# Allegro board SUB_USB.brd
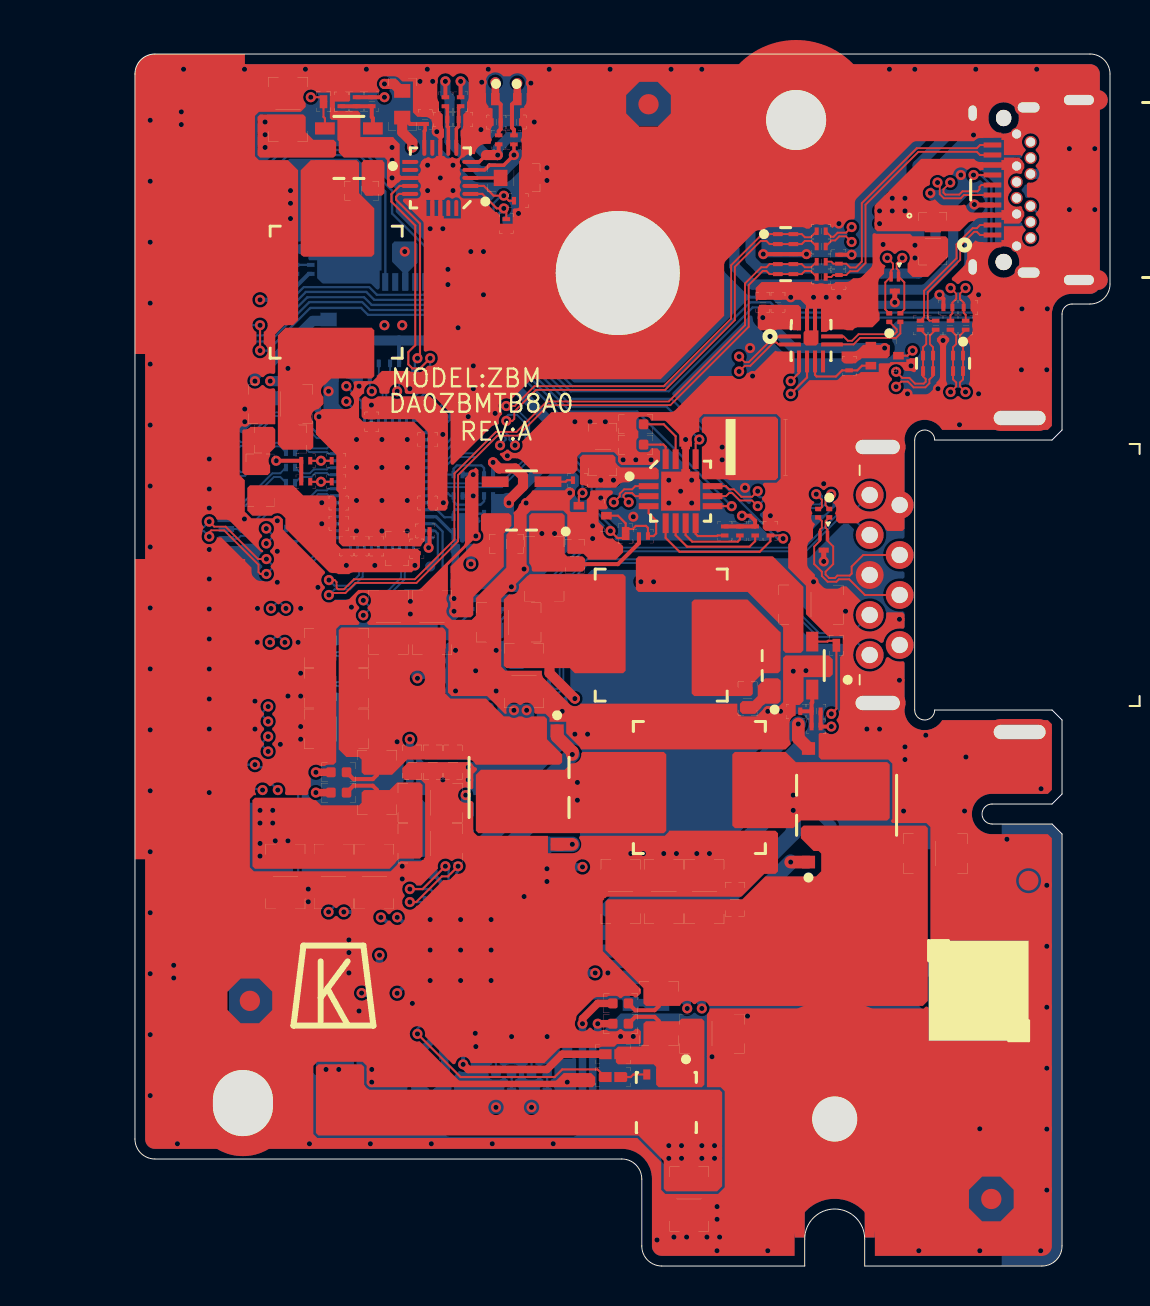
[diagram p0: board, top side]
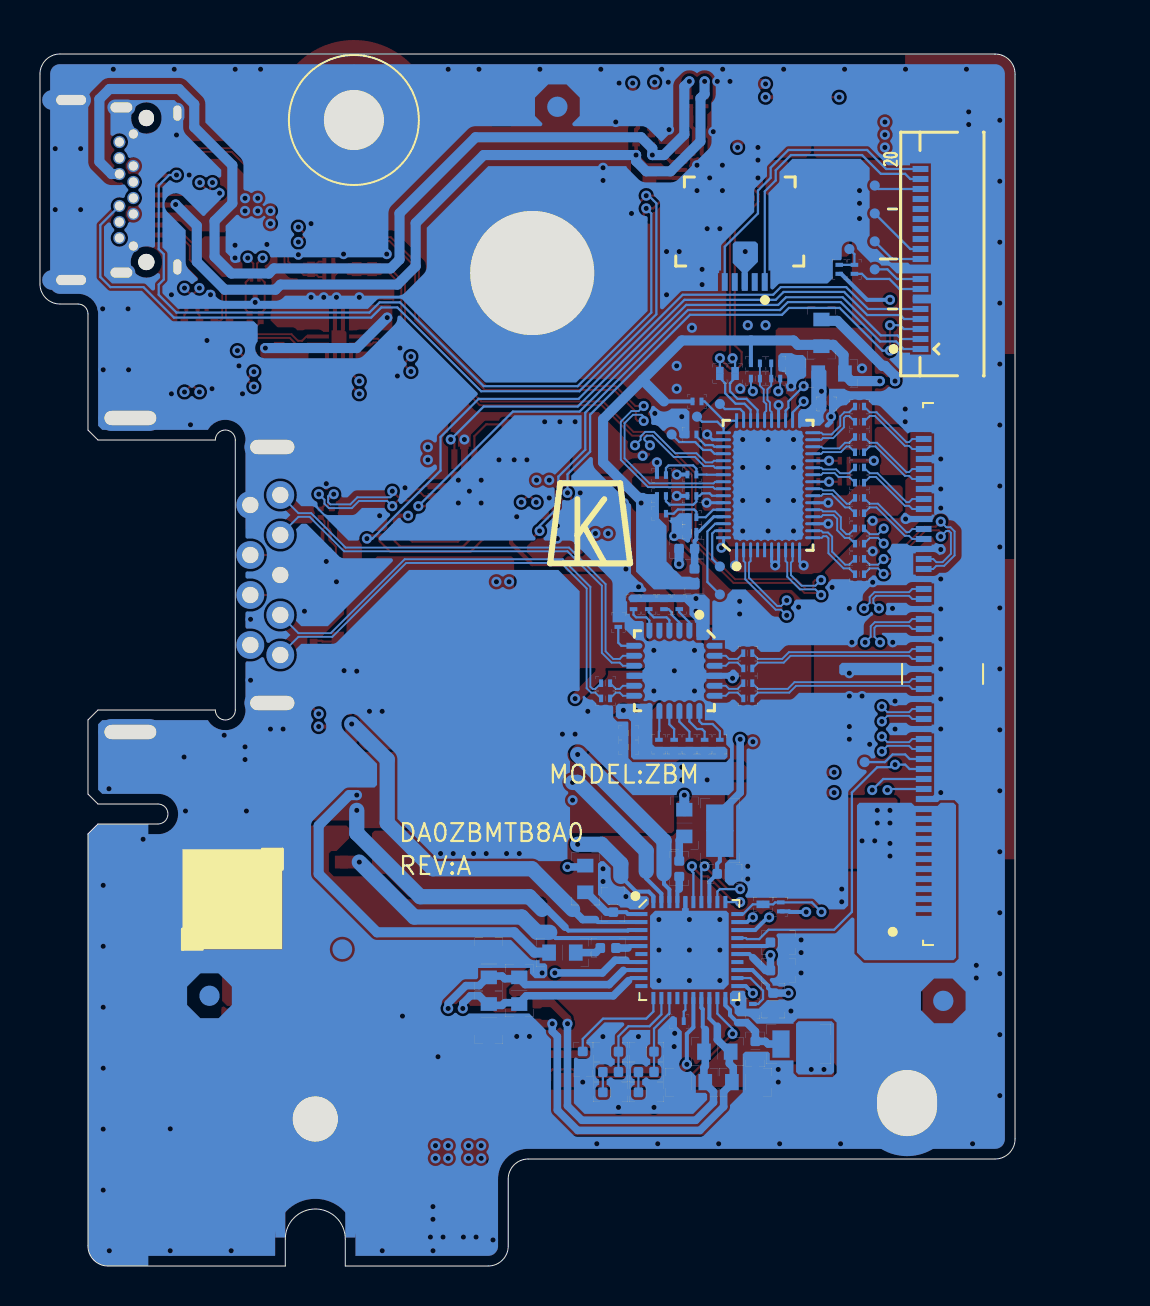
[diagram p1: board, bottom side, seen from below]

Outline 48.77 x 60.6 mm; copper layers: TOP, SGND, IN1, IN2, IN3, IN4, IN5, BOTTOM. Coordinates in mm from the lower left corner of the outline.
Outline path: 0,59.6 arc(0.29,60.31) 1,60.6 47.77,60.6 arc(48.48,60.31) 48.77,59.6 48.77,49.1 arc(48.48,48.39) 47.77,48.1 46.87,48.1 arc(46.52,47.95) 46.37,47.6 46.37,41.8 45.87,41.3 40,41.3 arc(39.5,41.8) 39,41.3 39,27.8 arc(39.5,27.3) 40,27.8 45.87,27.8 46.37,27.3 46.37,23.6 45.87,23.1 42.87,23.1 arc(42.37,22.6) 42.87,22.1 45.87,22.1 46.37,21.6 46.37,1 arc(46.08,0.29) 45.37,0 36.5,0 36.5,1.35 arc(35,2.85) 33.5,1.35 33.5,0 26.35,0 arc(25.64,0.29) 25.35,1 25.35,4.35 arc(25.06,5.06) 24.35,5.35 1,5.35 arc(0.29,5.64) 0,6.35 0,59.6

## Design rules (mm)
constraint set DEFAULT: min track width 0.109
net group W20-T1234B: nets PP3300_USB_C1_G PP3300_USB_C1_U
net group DFP-S3.5(4.2: nets USB_A1_SSRX_C_N USB_A1_SSRX_C_P USB_A1_SSRX_N USB_A1_SSRX_P USB_A1_SSRX_U_N USB_A1_SSRX_U_P USB_A1_SSTX_C_N USB_A1_SSTX_C_P USB_A1_SSTX_N USB_A1_SSTX_P USB_A1_SSTX_U_N USB_A1_SSTX_U_P USB_C1_AUX_DC_N USB_C1_AUX_DC_P USB_C1_ML0_C_N USB_C1_ML0_C_P USB_C1_ML0_N USB_C1_ML0_P USB_C1_ML1_C_N USB_C1_ML1_C_P USB_C1_ML1_N USB_C1_ML1_P USB_C1_ML2_C_N USB_C1_ML2_C_P USB_C1_ML2_N USB_C1_ML2_P USB_C1_ML3_C_N USB_C1_ML3_C_P USB_C1_ML3_N USB_C1_ML3_P USB_C1_RX2_CON_N USB_C1_RX2_CON_P USB_C1_SSRX_C_N USB_C1_SSRX_C_P USB_C1_SSTX_C_N USB_C1_SSTX_C_P USB_C1_TX2_CON_N USB_C1_TX2_CON_P USB_C1_USB2_U_N USB_C1_USB2_U_P
net group W20-T124B: nets USB_C1_CC1 USB_C1_CC1_C USB_C1_CC2 USB_C1_CC2_C

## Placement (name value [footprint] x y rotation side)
C1  0.22u/6.3V_2  [C0201]  13.37 29.14 0 bottom
C2  0.22u/6.3V_2  [C0201]  13.37 28.38 0 bottom
C3  0.1u/6.3V_2  [C0201]  19.34 26.67 0 bottom
C4  0.1u/6.3V_2  [C0201]  19.34 25.93 0 bottom
C5  0.22u/6.3V_2  [C0201]  20.48 28.38 0 bottom
C6  0.22u/6.3V_2  [C0201]  20.48 29.14 0 bottom
C7  1u/6.3V_2  [C0201]  14.51 36.75 180 top
C8  0.1u/6.3V_2  [C0201]  9.43 43.1 180 bottom
C22  22p/50V_2  [C0201]  11.84 58.22 270 top
C23  *220p/25V_2  [C0201]  19.08 57.2 0 top
C24  *220p/25V_2  [C0201]  18.07 57.2 180 top
C25  22u/10V_8  [C0805]  18.7 32.18 0 top
C98  22u/6.3V_6  [C0603]  23.4 40.82 270 top
C146  0.22u/10V_2  [C0201]  7.78 37.64 0 bottom
C156  0.22u/6.3V_2  [C0201]  13.37 29.88 0 bottom
C157  0.22u/6.3V_2  [C0201]  13.37 30.64 0 bottom
C160  150u/6.3V_3528H1.9  [C3528]  32.54 40.94 180 top
C161  0.1u/25V_2  [C0201]  11.97 44.37 0 bottom
C162  0.1u/25V_2  [C0201]  12.99 44.37 180 bottom
C165  0.1u/6.3V_2  [C0201]  31.4 48.18 90 top
C166  1u/6.3V_2  [C0201]  32.16 48.18 90 top
C167  1u/6.3V_2  [C0201]  14.51 57.33 90 top
C168  0.33u/25V_2  [C0201]  40.79 47.04 90 top
C169  0.33u/25V_2  [C0201]  41.55 47.04 90 top
C170  0.22u/10V_2  [C0201]  39.29 47.04 90 top
C171  0.22u/10V_2  [C0201]  40.05 47.04 90 top
C172  0.33u/25V_2  [C0201]  34.32 49.45 0 top
C173  0.33u/25V_2  [C0201]  34.32 50.21 0 top
C175  0.22u/10V_2  [C0201]  34.32 50.98 0 top
C176  0.22u/10V_2  [C0201]  34.32 51.74 0 top
C177  0.1u/50V_6  [C0603]  18.96 54.41 180 top
C181  0.1u/50V_6  [C0603]  39.91 51.36 90 top
C182  10u/35V_8  [C0805]  27.72 3.35 90 top
C183  22u/25V_8  [C0805]  40.04 20.62 180 top
C187  4.7u/6.3V_4  [C0402_2]  11.84 14.78 0 bottom
C188  22u/25V_8  [C0805]  24.29 18.72 270 top
C189  4.7u/25V_6  [C0603]  14.89 10.72 180 bottom
C192  22u/25V_8  [C0805]  28.48 18.72 270 top
C193  22u/25V_8  [C0805]  26.45 18.72 270 top
C194  0.1u/25V_4  [C0402]  30 18.34 270 top
C197  0.47u/50V_6  [C0603]  22.64 15.67 0 bottom
C198  0.47u/50V_6  [C0603]  16.54 22.15 90 bottom
C199  0.1u/25V_4  [C0402]  13.88 25.2 90 top
C200  4.7u/10V_4  [C0402_2]  12.1 13.26 90 bottom
C201  22u/25V_8  [C0805]  12.68 32.18 270 top
C202  4.7u/10V_4  [C0402_2]  20.1 18.08 270 bottom
C203  22u/25V_8  [C0805]  14.87 32.18 270 top
C204  22u/25V_8  [C0805]  10.07 30.91 0 top
C213  22u/25V_8  [C0805]  10.07 26.85 0 top
C214  22u/25V_8  [C0805]  10.07 28.88 0 top
C215  22u/25V_8  [C0805]  11.97 19.48 90 top
C216  22u/25V_8  [C0805]  14.76 21.13 180 top
C217  22u/25V_8  [C0805]  14.76 23.16 180 top
C218  22u/25V_8  [C0805]  9.94 19.48 90 top
C219  22u/25V_8  [C0805]  7.53 19.48 90 top
C249  22u/25V_8  [C0805]  7.65 57.83 270 top
C250  22u/25V_8  [C0805]  33.81 33.07 180 top
C254  0.1u/50V_4  [C0402]  30.64 28.37 270 top
C255  0.1u/50V_4  [C0402]  11.34 53.77 0 top
C258  100p/25V_2  [C0201]  34.07 27.74 180 top
C259  22u/10V_8  [C0805]  7.27 43.1 0 top
C260  22u/10V_8  [C0805]  19.46 29.51 90 top
C748  0.01u/10V_2  [C0201]  11.84 42.21 270 top
C1006  0.068u/50V_6  [C0603]  13.49 9.19 0 bottom
C1007  4700p/50V_4  [C0402]  20.23 8.69 0 bottom
C1008  *0.1u/25V_4  [C0402]  20.23 10.72 180 bottom
C1009  4700p/50V_4  [C0402]  18.45 8.69 0 bottom
C1010  *0.1u/25V_4  [C0402]  18.45 10.72 180 bottom
C1011  4.7u/6.3V_4  [C0402_2]  11.84 16.18 0 bottom
C1012  2.2u/10V_4  [C0402]  14.51 19.61 0 bottom
C1013  *0.068u/50V_6  [C0603]  16.16 9.19 180 bottom
C1014  1u/25V_4  [C0402]  14.89 25.2 90 top
C1015  1u/25V_4  [C0402]  15.91 25.2 90 top
C1016  *0.068u/50V_6  [C0603]  26.32 12.43 90 bottom
C1017  4.7u/25V_6  [C0603]  24.8 13.77 270 bottom
C1018  0.068u/50V_6  [C0603]  26.32 15.1 270 bottom
C1019  1u/10V_4  [C0402]  22 35.48 270 top
C1020  1u/10V_4  [C0402]  18.57 36.12 180 top
C1021  1u/6.3V_2  [C0201]  16.16 39.57 180 bottom
C1022  4.7u/6.3V_4  [C0402_2]  13.11 35.86 270 top
C1023  0.01u/10V_2  [C0201]  14.64 41.32 180 top
C1024  *0.1u/25V_4  [C0402]  12.99 10.84 90 bottom
C1025  0.01u/10V_2  [C0201]  14.64 38.15 180 top
C1026  0.1u/6.3V_2  [C0201]  10.19 38.15 0 top
C1027  0.1u/6.3V_2  [C0201]  10.19 37.13 0 top
C1028  0.1u/6.3V_2  [C0201]  14.1 35.86 90 top
C1029  0.1u/6.3V_2  [C0201]  11.34 35.99 90 top
C1030  0.1u/6.3V_2  [C0201]  10.57 35.99 90 top
C1031  1u/6.3V_2  [C0201]  16.16 36.71 180 bottom
C1032  0.22u/10V_2  [C0201]  7.78 38.4 0 bottom
C1033  0.22u/10V_2  [C0201]  7.78 39.17 0 bottom
C1034  0.22u/10V_2  [C0201]  7.78 39.93 0 bottom
C1035  0.22u/10V_2  [C0201]  7.78 40.69 0 bottom
C1036  0.22u/10V_2  [C0201]  7.78 41.45 0 bottom
C1037  0.22u/10V_2  [C0201]  7.78 42.21 0 bottom
C1038  0.22u/10V_2  [C0201]  7.78 42.98 0 bottom
C1039  0.22u/10V_2  [C0201]  7.78 35.36 0 bottom
C1040  0.22u/10V_2  [C0201]  7.78 34.59 0 bottom
C1041  0.22u/10V_2  [C0201]  7.78 36.88 0 bottom
C1042  0.22u/10V_2  [C0201]  7.78 36.12 0 bottom
C1046  0.01u/10V_2  [C0201]  12.1 35.99 90 top
C1047  22u/25V_8  [C0805]  28.86 11.61 180 top
CN1  50506-00601-V01  [FPC-50506-00601-V01-6P-L]  13.77 52.25 0 bottom
D1  PE3620M1Q  [D-1X0_6-D24V0L1B2LPS]  38.26 51.74 270 top
D7  PUSB3FR4  [ESD10-2_5X1-5-0_5H]  40.42 45.13 180 top
D8  PUSB3FR4  [ESD10-2_5X1-5-0_5H]  32.54 50.6 270 top
D2741  PESD5V0X2UM  [D3-1X0_6-3P]  38.01 49.07 90 top
D2744  PESD5V0X2UM  [D3-1X0_6-3P]  34.45 36.12 90 top
D2745  PJE24VM5FN2  [D-1X0_6-2P-PJE24VM5FN2]  17.69 58.34 180 top
D2746  PJE24VM5FN2  [D-1X0_6-2P-PJE24VM5FN2]  19.46 58.34 0 top
HOLE18  *2D-BARCODE-5X5-S  [2D-BARCODE-5X5-S]  39.15 18.34 180 bottom
HOLE19  *2D-BARCODE-5X5-S  [2D-BARCODE-5X5-S]  42.2 13.77 90 top
HOLE20  *H-TC315IBC217D118P2  [H-TC315IBC217D118P2]  33.07 57.3 0 top
HOLE21  *H-C354D244P2  [H-C354D244P2]  24.15 49.65 0 top
HOLE22  *H-O197X209D118X130P2  [H-O197X209D118X130P2]  5.4 8.15 0 top
HOLE23  *H-TS3BS3D146P2  [H-TS3BS3D146P2]  35 7.35 0 top
HOLE24  *SPAD-ZBM-USB_B-1NP  [SPAD-ZBM-USB_B-1NP]  2.75 53.1 0 top
HOLE25  *SPAD-RE217X591NP  [SPAD-RE217X591NP]  2.76 27.84 0 top
HOLE26  *SPAD-C354NP  [SPAD-C354NP]  18 14.85 0 top
HOLE27  *SPAD-ZBM-USB_B-3NP  [SPAD-ZBM-USB_B-3NP]  44.86 11.05 0 bottom
J10  30154-00902-V01  [UB3-30154-00902-V01-9P]  44.25 34.55 90 top
J11  UT11113-1220Q-7H  [UB31-UT11113-1220Q-7H-24P]  43.45 53.8 90 top
J12  50696-0200M-V02  [50696-0200M-V02-20P-L]  2.23 50.6 90 bottom
J13  196650-50041-3  [FPC-196650-50041-3-50P-L]  1.97 29.6 90 bottom
L5  NFP0QHB542HS2D  [FILTER-NFP0QHB542HS2D-4P-SMT]  38.01 47.42 0 top
L6  NFP0QHB542HS2D  [FILTER-NFP0QHB542HS2D-4P-SMT]  34.45 37.64 180 top
L9  2.2uH_7.3x6.8x2.0  [L6_6X6_6-1_8H]  28.23 23.93 180 top
L15  6.8uH_6.6x7.4x1.8  [L6_6X6_6-1_6H]  10.07 48.69 270 top
L16  6.8uH_6.6x7.4x1.8  [L6_6X6_6-1_6H]  26.32 31.55 180 top
NOREF  -  [unnamed]  5.75 13.26 0 top
NOREF#2  -  [#2]  9.94 14.02 0 top
NOREF#3  -  [#2]  111.41 -8.21 0 top
NOREF#4  -  [#2]  60.61 -48.85 0 top
NOREF#5  -  [unnamed]  42.83 3.35 0 top
NOREF#6  -  [unnamed]  25.69 58.09 0 top
NOREF#7  -  [#2]  21.24 37.13 180 bottom
NOREF#8  -  [unnamed]  22.89 57.96 180 bottom
NOREF#9  -  [unnamed]  40.29 13.51 180 bottom
NOREF#10  -  [unnamed]  3.59 13.26 180 bottom
Q1  DMG1012T-7  [SOT23-1_38-5-3P]  37.5 45.52 180 top
Q38  PJE138K  [SOT23-1_38-5-3P]  22.89 37.51 180 top
Q1000  AONR32314  [DFN-8L-3X3-65-5P-0_9H]  26.58 8.18 90 top
Q1001  AON6998  [POWER-5X6-1_27-7P-0_8H]  35.59 23.04 0 top
Q1008  AON6998  [POWER-5X6-1_27-7P-0_8H]  19.21 23.93 180 top
R4  *0_5%_2  [R0201]  15.53 26.08 90 bottom
R5  *0_5%_2  [R0201]  17.05 26.08 90 bottom
R6  *0_5%_2  [R0201]  14.76 26.08 90 bottom
R7  *0_5%_2  [R0201]  16.29 26.08 90 bottom
R8  *4.99K_1%_2  [R0201]  19.84 32.18 90 bottom
R9  *0_5%_2  [R0201]  16.8 33.07 90 bottom
R10  *0_5%_2  [R0201]  18.32 33.07 90 bottom
R11  *0_5%_2  [R0201]  19.08 33.07 90 bottom
R12  *0_5%_2  [R0201]  17.56 33.07 90 bottom
R15  *Short_0201  [S0201]  14 44.63 90 bottom
R16  *Short_0201  [S0201]  14.76 44.63 90 bottom
R20  0_5%_6  [R0603]  13.37 58.09 90 top
R21  0_5%_6  [R0603]  9.68 46.66 90 bottom
R22  499K_1%_2  [R0201]  11.72 17.96 270 bottom
R23  *Short_0201  [S0201]  9.43 58.22 270 top
R24  *Short_0201  [S0201]  35.08 31.04 90 top
R25  100K_1%_2  [R0201]  35.72 45.01 270 top
R37  1K_1%_2  [R0201]  8.03 49.83 90 bottom
R84  10K_5%_2  [R0201]  17.69 39.55 180 bottom
R182  0_5%_6  [R0603]  6.26 39.29 90 top
R210  100K_5%_2  [R0201]  12.99 45.13 180 bottom
R211  100K_5%_2  [R0201]  11.97 45.13 180 bottom
R220  220K_1%_2  [R0201]  40.66 47.93 180 top
R221  220K_1%_2  [R0201]  41.68 47.93 0 top
R222  220K_1%_2  [R0201]  35.21 49.33 270 top
R223  220K_1%_2  [R0201]  35.21 50.34 90 top
R224  2_1%_4  [R0402]  24.29 12.11 0 top
R226  0_5%_4  [R0402]  24.29 13.13 180 top
R227  1.65K_1%_4  [R0402]  21.62 10.34 90 bottom
R266  0_1%_6  [R0603]  7.27 41.35 0 top
R267  0_1%_8  [R0805]  20.48 34.85 270 top
R268  100K_1%_2  [R0201]  11.08 58.22 270 top
R269  100K_1%_2  [R0201]  10.32 58.22 90 top
R270  13.7K_1%_2  [R0201]  33.05 27.74 180 top
R271  102K_1%_2  [R0201]  34.07 26.97 180 top
R375  100K_5%_2  [R0201]  31.78 36.75 90 top
R1000  *Short_0402  [S0402]  23.91 9.45 0 top
R1001  0_1%_8  [R0805]  10.83 11.1 180 bottom
R1002  *Short_0402  [S0402]  23.91 10.59 0 top
R1003  6.98K_1%_4  [R0402]  20.23 9.7 180 bottom
R1004  4.7_1%_6  [R0603]  21.5 19.35 270 bottom
R1005  3.48K_1%_4  [R0402]  18.45 9.7 180 bottom
R1006  0_5%_4  [R0402]  20.35 15.9 0 bottom
R1007  0_5%_4  [R0402]  16.8 19.86 270 bottom
R1008  *10K_1%_2  [R0201]  13.11 12.88 90 bottom
R1009  133K_1%_2  [R0201]  16.8 12.24 0 bottom
R1010  *Short_0201  [S0201]  12.61 18.08 180 bottom
R1011  *Short_0805  [S0805]  14.76 21.77 270 bottom
R1012  0_5%_4  [R0402]  10.19 24.69 180 top
R1013  2_1%_4  [R0402]  10.19 23.67 0 top
R27288  2M_5%_2  [R0201]  19.18 53.26 0 top
R27302  100K_5%_2  [R0201]  31.02 36.75 270 top
R27303  100K_5%_2  [R0201]  30.26 36.75 270 top
R27304  100K_5%_2  [R0201]  29.5 36.75 270 top
R27305  29.4K_1%_4  [R0402]  25.05 41.07 0 top
R27306  48.7K_1%_4  [R0402]  25.05 42.09 0 top
R27307  100K_5%_2  [R0201]  25.43 36.5 0 top
R27309  4.99K_1%_2  [R0201]  16.16 41.58 0 bottom
R27310  0_5%_4  [R0402]  16.03 34.47 270 bottom
R27311  *0_5%_4  [R0402]  16.42 35.86 0 bottom
R27312  0_5%_6  [R0603]  9.18 44.63 180 bottom
R27313  *4.7K_1%_2  [R0201]  8.54 39.21 0 top
R27314  *4.7K_1%_2  [R0201]  10.07 39.21 0 top
R27315  *4.7K_1%_2  [R0201]  8.54 40.26 0 top
R27316  *4.7K_1%_2  [R0201]  10.07 40.26 0 top
R27317  *4.7K_1%_2  [R0201]  17.69 37.62 180 bottom
R27318  *4.7K_1%_2  [R0201]  16.16 37.44 0 bottom
R27319  *4.7K_1%_2  [R0201]  17.69 38.5 180 bottom
R27320  *4.7K_1%_2  [R0201]  16.16 38.5 0 bottom
R27325  2M_5%_2  [R0201]  18.57 52.12 270 top
R27327  4.7K_1%_2  [R0201]  15.91 43.23 0 bottom
R27329  100K_5%_2  [R0201]  8.8 49.83 90 bottom
R27331  10K_1%_2  [R0201]  22.13 39.29 0 top
R27332  *4.7K_1%_2  [R0201]  17.81 26.08 90 bottom
R27333  *Short_0201  [S0201]  24.54 36.63 90 top
R91340  0_5%_2  [R0201]  18.96 56.31 90 top
R91341  0_5%_2  [R0201]  18.19 56.31 90 top
R91345  *0_5%_2  [R0201]  16.29 58.22 90 top
R91346  *0_5%_2  [R0201]  15.53 58.22 90 top
R91347  0_5%_2  [R0201]  15.4 57.33 0 top
R91348  0_5%_2  [R0201]  16.42 57.33 180 top
TP93  *TP  [TP2050]  14.76 43.1 180 bottom
TP95  *TP  [TP2050]  15.91 42.47 180 bottom
TP99  *TP  [TP2050]  14.76 34.97 180 bottom
TP100  *TP  [TP2050]  14.76 33.58 180 bottom
TP103  *TP  [TP2050]  17.18 41.58 180 bottom
TP105  *TP  [TP2050]  7.02 49.83 180 bottom
TP106  *TP  [TP2050]  8.29 50.85 180 bottom
TP107  *TP  [TP2050]  7.02 51.23 180 bottom
TP108  *TP  [TP2050]  7.02 52.63 180 bottom
TP109  *TP  [TP2050]  7.02 54.02 180 bottom
TP110  *TP  [TP2050]  7.53 25.2 180 bottom
U1  PS8719ETQFN24GTR2-A0  [QFN24-4X4-5-25P-9DBL02]  17.04 29.76 0 bottom
U2  PS8762QFN52GTR-A3  [QFN52-6_5X4_5-35-53P-0_8H]  12.35 39.04 180 bottom
U3  SY21041ABC  [SOT23-2_85-95-6P-1_4H]  10.7 55.93 0 top
U4  SY21113IADC  [SOT23-2_85-95-6P-1H]  32.93 30.02 270 top
U7  PI3USB9201ZTAEX  [QFN12-2X2-4]  33.81 46.28 270 top
U8  TPD6S300ARUKR  [QFN20-3X3-4-21P-TPD6S300]  15.27 54.41 90 top
U9  RAA489000ARGNP#HA0  [QFN40-5X5-4-41P-1H]  16.29 15.8 270 bottom
U18  0.01_1%_8  [R0805]  26.19 12.62 270 top
U37  SLGC55545VTR  [QFN16-3X3-5-17P-SLGC55544C]  27.29 38.74 270 top
U1000  0.01_1%_8  [R0805]  12.1 24.18 270 top
U1001  RT9078-33GJ5  [TSOT23-5-2_7955-9395-5P]  19.34 38.28 0 top

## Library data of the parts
C1-C8 C22-C25 C98 C156 C157 C161 C162 C165-C169 C172 C173 C177 C181-C183 C187-C189 C192-C194 C197-C204 C213-C219 C249 C250 C254 C255 C258-C260 C748 C1006-C1031 C1046 C1047 = CAP_NON-POL_BGM
C146 C170 C171 C175 C176 C1032-C1042 = CAP_NON-POL_V1_BGM
C160 = CAP_POL_BGM
CN1 = FFCFPC_6P_V2_BGM
D1 = TVS_DIODE_BGM
D7 D8 = PUSB3F96_10P_BGM
D2741 D2744 = PESD5V0X2UM_BGM
D2745 D2746 = TVS_DIODE_UNI_V2_BGM
HOLE18-HOLE27 = 3x2_6.1
J10 = USB3_TCR26-9V1391_13P_BGM
J11 = USB3_1_24P_8F_BGM
J12 = FFCFPC_20P_BGM
J13 = FFCFPC_50P_BGM
L5 L6 = BW_BGM
L9 L15 L16 = IND_V2_BGM
Q1 Q38 = MOS-N_3P_ESD_BGM
Q1000 = MOS-N_8P_SCH_BGM
Q1001 Q1008 = MOS-N-Dual_9P_BGM
R4-R12 R20-R22 R25 R37 R84 R182 R210 R211 R220-R224 R226 R227 R266-R271 R375 R1001 R1003-R1009 R1012 R1013 R27288 R27302-R27307 R27309-R27320 R27325 R27327 R27329 R27331 R27332 R91340 R91341 R91345-R91348 = RES_BGM
R15 R16 R23 R24 R1000 R1002 R1010 R1011 R27333 = SHORTPAD_V01_BGM
TP93 TP95 TP99 TP100 TP103 TP105-TP110 = TP_BGM
U1 = PS8719BTQFN24GTR-A0_24P_BGM
U2 = PS8802QFN52GTR-A1_52P_BGM_0
U3 = SY21041ABC_6P_V2_BGM
U4 = SY21113IADC_6P_V2_BGM
U7 = PI3USB9201ZTAEX_12P_V1_BGM
U8 = TPD6S300ARUKR_20P_BGM
U9 = ISL9237_19
U18 U1000 = R_Current_SEN_BGM
U37 = SLGC55545VTR_16P_BGM
U1001 = RT9078N-33GJ5_5P_BGM_0

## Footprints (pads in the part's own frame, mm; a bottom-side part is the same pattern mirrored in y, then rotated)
2D-BARCODE-5X5-S
  round 0.991 smd: 1(5.5,-2.5)
50696-0200M-V02-20P-L
  rect 0.305x0.787 smd: 1(-4.75,2.5) 2(-4.25,2.5) 3(-3.75,2.5) 4(-3.25,2.5) 5(-2.75,2.5) 6(-2.25,2.5) 7(-1.75,2.5) 8(-1.25,2.5) 9(-0.75,2.5) 10(-0.25,2.5) 11(0.25,2.5) 12(0.75,2.5) 13(1.25,2.5) 14(1.75,2.5) 15(2.25,2.5) 16(2.75,2.5) 17(3.25,2.5) 18(3.75,2.5) 19(4.25,2.5) 20(4.75,2.5)
  rect 0.406x0.787 smd: 21(-5.75,0) 22(5.75,0)
C0201
  rect 0.203x0.381 smd: 1(-0.225,0) 2(0.225,0)
C0402
  custom 0.12x0.12 smd: 1(0.39,0) 2(-0.39,0)
C0402_2
  custom 0.12x0.12 smd: 1(0.39,0) 2(-0.39,0)
C0603
  rect 0.686x0.813 smd: 1(0.6,0) 2(-0.6,0)
C0805
  rect 0.864x1.372 smd: 1(0.88,0) 2(-0.88,0)
C3528
  rect 1.6x2.591 smd: 1(1.5,0) 2(-1.5,0)
D3-1X0_6-3P
  rect 0.508x0.178 smd: 1(0.401,0.187) 2(0.401,-0.187)
  rect 0.254x0.508 smd: 3(-0.325,0)
D-1X0_6-2P-PJE24VM5FN2
  rect 0.432x0.61 smd: 1(-0.34,0) 2(0.34,0)
D-1X0_6-D24V0L1B2LPS
  rect 0.457x0.61 smd: 1(-0.375,0) 2(0.375,0)
DFN-8L-3X3-65-5P-0_9H
  rect 0.508x0.356 smd: 1(1.4,-0.975) 2(1.4,-0.325) 3(1.4,0.325) 4(1.4,0.975)
  custom 0.57x0.57 smd: 5(-0.51,0)
ESD10-2_5X1-5-0_5H
  rect 0.203x0.483 smd: 1(-1,-0.388) 2(-0.5,-0.388) 3(0,-0.388) 4(0.5,-0.388) 5(1,-0.388) 6(1,0.388) 7(0.5,0.388) 8(0,0.388) 9(-0.5,0.388) 10(-1,0.388)
FILTER-NFP0QHB542HS2D-4P-SMT
  rect 0.305x0.229 smd: 1(-0.278,-0.212) 2(-0.278,0.212) 3(0.278,0.212) 4(0.278,-0.212)
FPC-50506-00601-V01-6P-L
  rect 0.305x0.889 smd: 1(-1.25,3.05) 2(-0.75,3.05) 3(-0.25,3.05) 4(0.25,3.05) 5(0.75,3.05) 6(1.25,3.05)
  rect 0.991x2.007 smd: 7(-3.35,0) 8(3.35,0)
FPC-196650-50041-3-50P-L
  rect 0.305x0.787 smd: 1(-12.25,2.6) 2(-11.75,2.6) 3(-11.25,2.6) 4(-10.75,2.6) 5(-10.25,2.6) 6(-9.75,2.6) 7(-9.25,2.6) 8(-8.75,2.6) 9(-8.25,2.6) 10(-7.75,2.6) 11(-7.25,2.6) 12(-6.75,2.6) 13(-6.25,2.6) 14(-5.75,2.6) 15(-5.25,2.6) 16(-4.75,2.6) 17(-4.25,2.6) 18(-3.75,2.6) 19(-3.25,2.6) 20(-2.75,2.6) 21(-2.25,2.6) 22(-1.75,2.6) 23(-1.25,2.6) 24(-0.75,2.6) 25(-0.25,2.6) 26(0.25,2.6) 27(0.75,2.6) 28(1.25,2.6) 29(1.75,2.6) 30(2.25,2.6) 31(2.75,2.6) 32(3.25,2.6) 33(3.75,2.6) 34(4.25,2.6) 35(4.75,2.6) 36(5.25,2.6) 37(5.75,2.6) 38(6.25,2.6) 39(6.75,2.6) 40(7.25,2.6) 41(7.75,2.6) 42(8.25,2.6) 43(8.75,2.6) 44(9.25,2.6) 45(9.75,2.6) 46(10.25,2.6) 47(10.75,2.6) 48(11.25,2.6) 49(11.75,2.6) 50(12.25,2.6)
  rect 0.991x0.991 smd: 51(-13.55,0) 52(13.55,0)
H-C354D244P2
  round 9 hole 6.2: 1(0,0)
H-O197X209D118X130P2
  oval 5.004x5.309 hole 3x3.302: 1(0,0)
H-TC315IBC217D118P2
  round 8.001 hole 3: 1(0,0)
H-TS3BS3D146P2
  custom 2.25x2.25 hole 3.708: 1(0,0)
L6_6X6_6-1_6H
  rect 2.362x3.505 smd: 1(-3.025,0) 2(3.025,0)
L6_6X6_6-1_8H
  rect 2.362x3.505 smd: 1(-3.025,0) 2(3.025,0)
POWER-5X6-1_27-7P-0_8H
  rect 0.66x0.635 smd: 1(-1.905,-2.84) 5(1.905,2.84) 6(0.635,2.84) 7(-0.635,2.84) 8(-1.905,2.84)
  custom 0.488x0.488 smd: 2(0,-2.18)
  rect 3.988x2.667 smd: 9(0,0.795)
QFN12-2X2-4
  rect 0.203x1.092 smd: 1(-0.2,-1.05) 2(0.2,-1.05) 7(0.2,1.05) 8(-0.2,1.05)
  rect 1.092x0.203 smd: 3(1.05,-0.6) 4(1.05,-0.2) 5(1.05,0.2) 6(1.05,0.6) 9(-1.05,0.6) 10(-1.05,0.2) 11(-1.05,-0.2) 12(-1.05,-0.6)
QFN16-3X3-5-17P-SLGC55544C
  rect 0.305x0.991 smd: 1(-0.75,-1.6) 2(-0.25,-1.6) 3(0.25,-1.6) 4(0.75,-1.6) 9(0.75,1.6) 10(0.25,1.6) 11(-0.25,1.6) 12(-0.75,1.6)
  rect 0.991x0.305 smd: 5(1.6,-0.75) 6(1.6,-0.25) 7(1.6,0.25) 8(1.6,0.75) 13(-1.6,0.75) 14(-1.6,0.25) 15(-1.6,-0.25) 16(-1.6,-0.75)
  rect 1.702x1.702 smd: 17(0,0)
QFN20-3X3-4-21P-TPD6S300
  custom 0.05x0.05 smd: 1(-0.8,-1.5) 2(-0.4,-1.5) 3(0,-1.5) 4(0.4,-1.5) 5(0.8,-1.5) 6(1.5,-0.8) 7(1.5,-0.4) 8(1.5,0) 9(1.5,0.4) 10(1.5,0.8) 11(0.8,1.5) 12(0.4,1.5) 13(0,1.5) 14(-0.4,1.5) 15(-0.8,1.5) 16(-1.5,0.8) 17(-1.5,0.4) 18(-1.5,0) 19(-1.5,-0.4) 20(-1.5,-0.8)
  rect 1.803x1.803 smd: 21(0,0)
QFN24-4X4-5-25P-9DBL02
  custom 0.075x0.075 smd: 1(-1.25,-2) 2(-0.75,-2) 3(-0.25,-2) 4(0.25,-2) 5(0.75,-2) 6(1.25,-2) 7(2,-1.25) 8(2,-0.75) 9(2,-0.25) 10(2,0.25) 11(2,0.75) 12(2,1.25) 13(1.25,2) 14(0.75,2) 15(0.25,2) 16(-0.25,2) 17(-0.75,2) 18(-1.25,2) 19(-2,1.25) 20(-2,0.75) 21(-2,0.25) 22(-2,-0.25) 23(-2,-0.75) 24(-2,-1.25)
  rect 2.692x2.692 smd: 25(0,0)
QFN40-5X5-4-41P-1H
  rect 0.203x0.61 smd: 1(-1.8,-2.4) 2(-1.4,-2.4) 3(-1,-2.4) 4(-0.6,-2.4) 5(-0.2,-2.4) 6(0.2,-2.4) 7(0.6,-2.4) 8(1,-2.4) 9(1.4,-2.4) 10(1.8,-2.4) 21(1.8,2.4) 22(1.4,2.4) 23(1,2.4) 24(0.6,2.4) 25(0.2,2.4) 26(-0.2,2.4) 27(-0.6,2.4) 28(-1,2.4) 29(-1.4,2.4) 30(-1.8,2.4)
  rect 0.61x0.203 smd: 11(2.4,-1.8) 12(2.4,-1.4) 13(2.4,-1) 14(2.4,-0.6) 15(2.4,-0.2) 16(2.4,0.2) 17(2.4,0.6) 18(2.4,1) 19(2.4,1.4) 20(2.4,1.8) 31(-2.4,1.8) 32(-2.4,1.4) 33(-2.4,1) 34(-2.4,0.6) 35(-2.4,0.2) 36(-2.4,-0.2) 37(-2.4,-0.6) 38(-2.4,-1) 39(-2.4,-1.4) 40(-2.4,-1.8)
  rect 3.607x3.607 smd: 41(0,0)
QFN52-6_5X4_5-35-53P-0_8H
  custom 0.038x0.038 smd: 1(-1.575,-3.225) 2(-1.225,-3.225) 3(-0.875,-3.225) 4(-0.525,-3.225) 5(-0.175,-3.225) 6(0.175,-3.225) 7(0.525,-3.225) 8(0.875,-3.225) 9(1.225,-3.225) 10(1.575,-3.225) 11(2.225,-2.625) 12(2.225,-2.275) 13(2.225,-1.925) 14(2.225,-1.575) 15(2.225,-1.225) 16(2.225,-0.875) 17(2.225,-0.525) 18(2.225,-0.175) 19(2.225,0.175) 20(2.225,0.525) 21(2.225,0.875) 22(2.225,1.225) 23(2.225,1.575) 24(2.225,1.925) 25(2.225,2.275) 26(2.225,2.625) 27(1.575,3.225) 28(1.225,3.225) 29(0.875,3.225) 30(0.525,3.225) 31(0.175,3.225) 32(-0.175,3.225) 33(-0.525,3.225) 34(-0.875,3.225) 35(-1.225,3.225) 36(-1.575,3.225) 37(-2.225,2.625) 38(-2.225,2.275) 39(-2.225,1.925) 40(-2.225,1.575) 41(-2.225,1.225) 42(-2.225,0.875) 43(-2.225,0.525) 44(-2.225,0.175) 45(-2.225,-0.175) 46(-2.225,-0.525) 47(-2.225,-0.875) 48(-2.225,-1.225) 49(-2.225,-1.575) 50(-2.225,-1.925) 51(-2.225,-2.275) 52(-2.225,-2.625)
  rect 3.2x5.207 smd: 53(0,0)
R0201
  rect 0.203x0.381 smd: 1(-0.225,0) 2(0.225,0)
R0402
  custom 0.12x0.12 smd: 1(0.39,0) 2(-0.39,0)
R0603
  rect 0.686x0.813 smd: 1(0.6,0) 2(-0.6,0)
R0805
  rect 0.864x1.372 smd: 1(0.88,0) 2(-0.88,0)
S0201
  rect 0.343x0.381 smd: 1(-0.225,0) 2(0.225,0)
S0402
  custom 0.125x0.125 smd: 1(0.39,0) 2(-0.39,0)
S0805
  rect 1.346x1.372 smd: 1(0.88,0) 2(-0.88,0)
SOT23-1_38-5-3P
  rect 0.533x0.381 smd: 1(0.69,0.5) 2(0.69,-0.5) 3(-0.69,0)
SOT23-2_85-95-6P-1_4H
  rect 0.991x0.61 smd: 1(1.2,-0.95) 2(1.2,0) 3(1.2,0.95) 4(-1.2,0.95) 5(-1.2,0) 6(-1.2,-0.95)
SOT23-2_85-95-6P-1H
  rect 0.991x0.61 smd: 1(1.2,-0.95) 2(1.2,0) 3(1.2,0.95) 4(-1.2,0.95) 5(-1.2,0) 6(-1.2,-0.95)
SPAD-C354NP
  round 9 smd: 1(0,0)
SPAD-RE217X591NP
  rect 5.512x15.011 smd: 1(0,0)
SPAD-ZBM-USB_B-1NP
  custom 1.375x1.375 smd: 1(0,0)
SPAD-ZBM-USB_B-3NP
  custom 0.755x0.755 smd: 1(0,0)
TP2050
  round 0.508 smd: 1(0,0)
TSOT23-5-2_7955-9395-5P
  rect 1.346x0.533 smd: 1(1.32,-0.94) 2(1.32,0) 3(1.32,0.94) 4(-1.32,0.94) 5(-1.32,-0.94)
UB3-30154-00902-V01-9P
  round 1.397 hole 0.813: 1(-3.5,6) 2(-1,6) 3(1,6) 4(3.5,6) 5(4,7.5) 6(2,7.5) 7(0,7.5) 8(-2,7.5) 9(-4,7.5)
  oval 1.295x3.2 hole 0.711x2.591: 10(-7.85,0) 11(7.85,0)
  oval 1.295x2.794 hole 0.711x2.21: 12(6.4,7.1) 13(-6.4,7.1)
UB31-UT11113-1220Q-7H-24P
  round 0.813 hole 0.813 unplated: (-3.6,0)
  oval 0.813x0.762 hole 0.813x0.762 unplated: (3.6,0)
  oval 1.041x0.711 hole 0.762x0.406: 1(-3.845,1.55) 2(3.845,1.55)
  oval 0.787x1.397 hole 0.508x1.092: 3(-4.13,-1.25) 4(4.13,-1.25)
  oval 0.991x2.438 hole 0.508x1.499: 5(-4.5,-3.765) 6(4.5,-3.765)
  rect 0.254x0.889 smd: A1(-2.75,0.56) A2(-2.25,0.56) A3(-1.75,0.56) A4(-1.25,0.56) A5(-0.75,0.56) A6(-0.25,0.56) A7(0.25,0.56) A8(0.75,0.56) A9(1.25,0.56) A10(1.75,0.56) A11(2.25,0.56) A12(2.75,0.56)
  round 0.61 hole 0.457: B1(2.8,-0.65) B2(2.4,-1.35) B3(1.6,-1.35) B4(1.2,-0.65) B5(0.8,-1.35) B6(0.4,-0.65) B7(-0.4,-0.65) B8(-0.8,-1.35) B9(-1.2,-0.65) B10(-1.6,-1.35) B11(-2.4,-1.35) B12(-2.8,-0.65)
unnamed
  round 1.016 smd: 1(0,0)

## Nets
3V3_FB: C22.2 R268.2 R269.1 U3.3
3V3_SW: C255.2 L15.1 U3.6(LX)
5V_FB: C258.2 R270.1 R271.2 U4.3
5V_SW: C254.2 L16.1 U4.6(LX)
GND: C3.2 C4.2 C7.2 C8.2 C23.2 C24.2 C25.2 C98.2 C160.2 C165.2 C166.2 C167.2 C177.2 C181.2 C182.2 C183.2 C187.2 C188.2 C192.2 C193.2 C194.2 C199.2 C200.2 C201.2 C202.2 C203.2 C204.2 C213.2 C214.2 C215.2 C216.2 C217.2 C218.2 C219.2 C249.2 C250.2 C259.2 C260.2 C748.2 C1006.2 C1007.2 C1008.2 C1009.2 C1010.2 C1011.2 C1012.2 C1013.2 C1014.2 C1015.2 C1016.2 C1018.2 C1019.2 C1020.2 C1021.1 C1022.2 C1023.2 C1024.2 C1025.2 C1026.2 C1027.2 C1028.2 C1029.2 C1030.2 C1031.1 C1046.2 C1047.2 CN1.6 CN1.7 CN1.8 D1.2 D7.3 D7.8 D8.3 D8.8 D2741.3 D2744.3 D2745.2 D2746.2 HOLE20.1 HOLE21.1 HOLE22.1 HOLE23.1 HOLE24.1 HOLE25.1 HOLE26.1 HOLE27.1 J10.4 J10.7 J10.10 J10.11 J10.12 J10.13 J11.1 J11.2 J11.3 J11.4 J11.5 J11.6 J11.A1 J11.A12 J11.B1 J11.B12 J12.6 J12.9 J12.20 J12.21 J12.22 J13.13 J13.20 J13.23 J13.26 J13.29 J13.32 J13.35 J13.38 J13.41 J13.44 J13.47 J13.50 J13.51 J13.52 Q38.1(S) Q1001.5 Q1001.6 Q1001.7(S2#3) Q1008.5 Q1008.6 Q1008.7(S2#3) R8.2 R211.2 R220.2 R221.2 R222.2 R223.2 R227.2 R269.2 R270.2 R375.2 R1008.1 R1009.2 R27288.2 R27305.2 R27306.2 R27309.2 R27314.2 R27316.2 R27318.2 R27320.2 R27325.2 R91347.1 R91348.1 U1.10 U1.21 U1.25 U2.53 U3.2 U4.2 U7.9 U7.10 U7.11 U8.8 U8.13 U8.16 U8.17 U8.18 U8.21 U9.36 U9.41 U37.14 U37.17 U1001.2
ADDR: R27313.2 R27314.1 U2.19
BTN_ANALOG: J13.17 TP110.1
CE_USB: R27327.1 U2.36
CEQ: R27317.2 R27318.1 U2.48
CHARGER_SUB_BATGONE: R1008.2 U9.22
CHARGER_SUB_CMPOUT_OD: R1010.1 U9.30
DPEQ: R27315.2 R27316.1 U2.22
EC_I2C_USB_C1_SCL: J13.14 U2.28 U7.3 U9.31 U9.35
EC_I2C_USB_C1_SDA: J13.15 U2.29 U7.4 U9.32 U9.34
EN_KB_BL: J12.11 TP108.1
EN_PP3300_SUB_S: R23.2 U3.4
EN_PP5000_PEN: J12.8 TP105.1
EN_PP5000_SUB_U: R24.2 U4.4
EN_SUB_RAILS: R22.1 R23.1 R24.1 R1010.2
EN_USB_A1_VBUS: J12.5 R375.1 U37.5
KB_BL_PWM: J12.10 TP107.1
LID_360_L: CN1.5 J12.19
LID_OPEN: CN1.1 J12.18
PEN_DET_ODL: J12.7 R37.1
PP1200_SUB_S: R182.1 R266.2
PP1200_SUB_S_R: C22.1 C259.1 L15.2 R266.1 R268.1
PP3300_SUB_LDO_G: C187.1 CN1.3 R20.1 R22.2 U9.25
PP3300_SUB_S: C3.1 C4.1 C1020.1 R4.1 R5.1 R6.1 R7.1 R9.2 R10.2 R11.2 R12.2 R21.1 R27329.1 R27332.1 U1.1 U1.13(VDD_2) U1001.5(VOUT)
PP3300_USB_C1_G: C165.1 C166.1 C167.1 Q1.2 R20.2 R25.1 R27311.1 U7.12(VDD) U8.10(VPWR)
PP3300_USB_C1_U: R21.2 R84.1 R210.1 R27310.1 R27312.1 R27313.1 R27315.1 R27317.1 R27319.1 R27327.2
PP5000_SUB_CHARGER_INT: C200.1 R1004.2 U9.23
PP5000_SUB_CHARGER_INT_R: C202.1 R1004.1 U9.1
PP5000_SUB_U: C98.1 C1019.1 R267.2 R1011.2 R27302.1 R27303.1 R27304.1 R27307.1 R27331.2 U37.1 U1001.1
PP5000_SUB_U_R: C25.1 C258.1 C260.1 L16.2 R267.1 R271.1
PP5000_USB_A1_VBUS: C160.1 J10.1(VBUS) U37.12(VOUT)
PP5000_USB_C1_VCONN: C1012.1 R1011.1 U9.33
PPVAR_SYS: C215.1 C216.1 C217.1 C218.1 C219.1 C249.1 C250.1 J13.1 J13.2 J13.3 J13.4 J13.5 J13.6 J13.7 J13.8 J13.9 J13.10 J13.11 J13.12 R1013.1 U3.5 U4.5 U9.7 U1000.1
PPVAR_SYS_N: C1017.2 C1018.1 R1013.2 U9.8
PPVAR_SYS_P: C1016.1 C1017.1 R1012.1 U9.9
PPVAR_SYS_R: C199.1 C201.1 C203.1 C204.1 C213.1 C214.1 C1014.1 C1015.1 Q1008.2 R1012.2 U9.21(VSYS) U1000.2
PPVAR_USB_C1_VBUS: C181.1 C182.1 D1.1 J11.A4 J11.A9 J11.B4 J11.B9(VBUS#4) Q1000.5 R1001.1
PPVAR_USB_C1_VIN: C1047.1 Q1000.1 Q1000.2 Q1000.3(S3) R224.1 R1002.1 U18.1
PPVAR_USB_C1_VIN_R: C183.1 C188.1 C192.1 C193.1 C194.1 Q1001.2 R226.2 U18.2
SSEQ: R27319.2 R27320.1 U2.46
SUB_CHARGER_COMPF: C1008.1 R1003.1 U9.12
SUB_CHARGER_COMPR: C1010.1 R1005.1 U9.13
USB_A0_STATUS_L: J12.1 R27333.1
USB_A1_CHARGE_EN_L: J12.3 Q38.2
USB_A1_ILIM_SEL: Q38.3 R27307.2 R27333.2 U37.4
USB_A1_OC_ODL: J12.4 U37.13
USB_A1_SSRX_C_N: C157.2 U1.23
USB_A1_SSRX_C_P: C156.2 U1.22
USB_A1_SSRX_N: C157.1 J13.28
USB_A1_SSRX_P: C156.1 J13.27
USB_A1_SSRX_U_N: J10.5 U1.8
USB_A1_SSRX_U_P: J10.6 U1.9
USB_A1_SSTX_C_N: C1.2 U1.20
USB_A1_SSTX_C_P: C2.2 U1.19
USB_A1_SSTX_CON_N: C6.2 J10.8
USB_A1_SSTX_CON_P: C5.2 J10.9
USB_A1_SSTX_N: C1.1 J13.25
USB_A1_SSTX_P: C2.1 J13.24
USB_A1_SSTX_U_N: C6.1 U1.11
USB_A1_SSTX_U_P: C5.1 U1.12
USB_A1_STATUS_L: J12.2 U37.9
USB_A1_USB2_L_N: D2744.1 J10.2 L6.3
USB_A1_USB2_L_P: D2744.2(K2) J10.3 L6.2
USB_A1_USB2_N: J13.22 U37.2
USB_A1_USB2_P: J13.21 U37.3
USB_A1_USB2_U_N: L6.4 U37.11
USB_A1_USB2_U_P: L6.1 U37.10
USB_C1_AUX_DC_N: C162.2 R210.2 U2.32
USB_C1_AUX_DC_P: C161.2 R211.1 U2.31
USB_C1_AUX_N: C162.1 J13.19
USB_C1_AUX_P: C161.1 J13.18
USB_C1_CC1: C23.1 D2746.1 R91340.2 U9.28
USB_C1_CC1_C: J11.A5 R91340.1 R91346.2 U8.4
USB_C1_CC2: C24.1 D2745.1 R91341.2 U9.29
USB_C1_CC2_C: J11.B5 R91341.1 R91345.2 U8.5
USB_C1_IBUS_N: C189.2 C1013.1 R226.1 U9.17
USB_C1_IBUS_P: C189.1 C1006.1 R224.2 U9.18
USB_C1_INT_G_ODL: Q1.1(S) R25.2 U7.5
USB_C1_INT_ODL: J13.16 Q1.3 U9.27
USB_C1_ML0_C_N: C1032.2 U2.18
USB_C1_ML0_C_P: C146.2 U2.17
USB_C1_ML0_N: C1032.1 J13.40
USB_C1_ML0_P: C146.1 J13.39
USB_C1_ML1_C_N: C1034.2 U2.21
USB_C1_ML1_C_P: C1033.2 U2.20
USB_C1_ML1_N: C1034.1 J13.43
USB_C1_ML1_P: C1033.1 J13.42
USB_C1_ML2_C_N: C1036.2 U2.24
USB_C1_ML2_C_P: C1035.2 U2.23
USB_C1_ML2_N: C1036.1 J13.46
USB_C1_ML2_P: C1035.1 J13.45
USB_C1_ML3_C_N: C1038.2 U2.26
USB_C1_ML3_C_P: C1037.2 U2.25
USB_C1_ML3_N: C1038.1 J13.49
USB_C1_ML3_P: C1037.1 J13.48
USB_C1_RX1_CON_N: C168.2 J11.B10 R220.1
USB_C1_RX1_CON_P: C169.2 J11.B11 R221.1
USB_C1_RX1_L_N: C168.1 D7.2 D7.9 U2.3
USB_C1_RX1_L_P: C169.1 D7.1 D7.10 U2.2
USB_C1_RX2_CON_N: C172.2 J11.A10 R222.1
USB_C1_RX2_CON_P: C173.2 J11.A11 R223.1
USB_C1_RX2_L_N: C172.1 D8.5 D8.6(NC#4) U2.8
USB_C1_RX2_L_P: C173.1 D8.4 D8.7 U2.9
USB_C1_SBU1_C: J11.A8 R27325.1 U8.1
USB_C1_SBU1_U: R15.2 U8.15
USB_C1_SBU2_C: J11.B8 R27288.1 U8.2
USB_C1_SBU2_U: R16.2 U8.14
USB_C1_SSRX_C_N: C1040.2 U2.11
USB_C1_SSRX_C_P: C1039.2 U2.12
USB_C1_SSRX_N: C1040.1 J13.37
USB_C1_SSRX_P: C1039.1 J13.36
USB_C1_SSTX_C_N: C1042.2 U2.14
USB_C1_SSTX_C_P: C1041.2 U2.15
USB_C1_SSTX_N: C1042.1 J13.34
USB_C1_SSTX_P: C1041.1 J13.33
USB_C1_TX1_CON_N: C170.2 J11.A3
USB_C1_TX1_CON_P: C171.2 J11.A2
USB_C1_TX1_L_N: C170.1 D7.5 D7.6(NC#4) U2.42
USB_C1_TX1_L_P: C171.1 D7.4 D7.7 U2.41
USB_C1_TX2_CON_N: C175.2 J11.B3
USB_C1_TX2_CON_P: C176.2 J11.B2
USB_C1_TX2_L_N: C175.1 D8.2 D8.9 U2.44
USB_C1_TX2_L_P: C176.1 D8.1 D8.10 U2.45
USB_C1_USB2_L_N: D2741.2(K2) J11.A7 J11.B7 L5.3
USB_C1_USB2_L_P: D2741.1 J11.A6 J11.B6 L5.2
USB_C1_USB2_N: J13.31 U7.2
USB_C1_USB2_P: J13.30 U7.1
USB_C1_USB2_U_N: L5.4 U7.7
USB_C1_USB2_U_P: L5.1 U7.8
USB_C1_VBUS_SENSE: C1024.1 R1001.2 U9.20
USB_C1_VBUS_VIN_GATE: R1000.2 U9.19
USB_C1_VBUS_VIN_SRC: R1002.2 U9.16
USB_C1_VX1: C197.1 L9.1 Q1001.9 U9.3
USB_C1_VX2: C198.1 L9.2 Q1008.9 U9.39
N18245155: R11.1 U1.6
N18245170: R10.1 U1.4
N18245175: R12.1 U1.3
N18245180: R9.1 U1.2
N18245515: R8.1 U1.7
N18245611: R6.2 U1.18
N18245626: R4.2 U1.17
N18245631: R7.2 U1.16
N18245636: R5.2 U1.15
N18248542: R91346.1 R91347.2 U8.7
N18248558: R91345.1 R91348.2 U8.6
N18248699: C177.1 U8.3
N18258732: C7.1 C8.1 R27312.2 U2.27 U2.52
N18270933: C254.1 U4.1
N18271452: C255.1 U3.1
N18295145: Q1000.4 R1000.1
N18295287: Q1001.1 U9.4
N18295291: Q1008.1 U9.38
N18295339: Q1001.8 U9.2
N18295351: Q1008.8 U9.40
N18295373: C197.2 R1006.1
N18295375: C198.2 R1007.2
N18295448: R1006.2 U9.5
N18295450: R1007.1 U9.37
N18295725: C1007.1 R1003.2
N18295735: C1009.1 R1005.2
N18295835: R1009.1 U9.15
N18295941: C1011.1 U9.26
N18296056: R227.1 U9.11
N18298566: R27304.2 U37.8
N18298568: R27303.2 U37.7
N18298570: R27302.2 U37.6
N18298637: R27306.1 U37.15
N18298641: R27305.1 U37.16
N18310730: R27309.1 U2.39
N18310842: TP93.1 U2.35
N18310878: TP95.1 U2.37
N18311237: TP99.1 U2.51
N18311298: TP100.1 U2.50
N18311691: R15.1 U2.33
N18311698: R16.1 U2.34
N18311970: C1031.2 R27310.2 R27311.2 U2.49
N18312906: C1021.2 R84.2 U2.43
N18314765: C748.1 C1022.1 C1023.1 C1025.1 C1026.1 C1027.1 C1028.1 C1029.1 C1030.1 C1046.1 R182.2 U2.1 U2.6 U2.7(VDD_R2) U2.10 U2.13 U2.16 U2.30 U2.38 U2.47
N18322467: TP103.1 U2.40
N18368928: R27331.1 U1001.3
N18394207: R27332.2 U1.14
N18445576: R37.2 R27329.2 TP106.1
N18445729: J12.17 TP109.1

Pads without a net: CN1 2 4; HOLE18 1; HOLE19 1; J12 12 13 14 15 16; NOREF 1; NOREF#5 1; NOREF#6 1; NOREF#8 1; NOREF#9 1; NOREF#10 1; U1 5 24; U2 4 5; U7 6; U8 9 11 12 19 20; U9 6 10 14 24; U1001 4

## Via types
v1: diameter 0.508, hole 0.254, TOP to BOTTOM, 448 vias

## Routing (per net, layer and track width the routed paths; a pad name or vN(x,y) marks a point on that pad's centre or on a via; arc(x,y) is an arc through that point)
3V3_FB: length 2.7
  TOP w0.203: U3.3 11.9,57.4 11.84,57.45 C22.2 R268.2 R269.1
5V_FB: length 2.4
  TOP w0.203: U4.3 33.88,28.18 33.84,28.14 C258.2 ; R271.2 C258.2 ; C258.2 R270.1
GND: length 17.7
  TOP w0.178: v1(12.86,54.41) U8.13
  TOP w0.203: R222.2 v1(35.21,48.44) ; v1(40.24,48.56) 40.44,48.37 R220.2 ; v1(33.59,50.6) D8.8 D8.3 v1(31.43,50.6) ; v1(35.85,50.57) R223.2 ; R375.2 v1(31.78,37.51) ; R270.2 v1(32.29,27.74)
  TOP w0.254: v1(41.94,56.55) J11.A12 ; D2744.3 v1(34.45,35.23) ; D2741.3 v1(38.01,48.18)
  TOP w0.305: U37.14 v1(27.54,41.32)
  TOP w0.381: D2745.2 v1(17.35,59.19)
  BOTTOM w0.203: C1021.1 v1(16.92,39.57) ; R1009.2 v1(17.02,11.63) ; R27320.2 v1(16.92,38.5) ; C8.2 v1(9.21,42.47)
  BOTTOM w0.305: J13.41 v1(5.47,37.35)
  BOTTOM w0.381: R227.2 v1(21.62,9.19) ; C1009.2 v1(18.06,7.93) ; C1010.2 v1(18.84,11.47) ; C202.2 v1(19.46,18.47) ; C1008.2 v1(20.62,11.47) ; C1007.2 v1(19.84,7.93)
  vias: v1(0.76,57.29) v1(0.76,54.24) v1(0.76,51.19) v1(0.76,48.14) v1(0.76,45.1) v1(0.76,42.05) v1(0.76,39) v1(0.76,35.95) v1(0.76,32.9) v1(0.76,29.86) v1(0.76,26.81) v1(0.76,23.76) v1(0.76,20.71) v1(0.76,17.66) v1(0.76,14.62) v1(0.76,11.57) v1(0.76,8.52) v1(1.94,15.04) v1(1.94,14.4) v1(2.12,6.11) v1(2.32,57.71) v1(2.32,57.07) v1(2.43,59.84) v1(3.72,40.35) v1(3.72,38.85) v1(3.72,37.9) v1(3.72,35.82) v1(3.72,34.35) v1(3.72,32.85) v1(3.72,31.35) v1(3.72,29.85) v1(3.72,28.35) v1(3.72,26.85) v1(3.72,23.67) v1(5.48,59.84) v1(5.49,42.85) v1(5.49,42.21) v1(6,28.24) v1(6,26.85) v1(6.13,32.88) v1(6.12,31.18) v1(7.12,37.26) v1(7.12,35.74) v1(7.12,34.19) v1(7.27,26.08) v1(7.65,28.5) v1(7.78,53.77) v1(7.78,53.14) v1(7.78,52.37) v1(8.16,31.18) v1(8.29,32.88) v1(8.29,29.64) v1(8.29,28.5) v1(8.29,26.97) v1(8.29,26.34) v1(8.53,59.84) v1(8.67,18.85) v1(8.67,18.21) v1(8.73,6.11) v1(9.15,33.93) v1(10.7,16.31) v1(10.7,15.67) v1(10.7,14.65) v1(10.83,32.94) v1(11.08,41.32) v1(11.08,39.93) v1(11.08,38.28) v1(11.08,36.75) v1(11.21,43.99) v1(11.21,12.75) v1(11.57,59.84) v1(11.84,9.83) v1(11.84,9.19) v1(11.78,6.11) v1(12.35,41.32) v1(12.35,39.93) v1(12.35,38.28) v1(12.35,36.75) v1(12.48,47.04) v1(12.86,55.93) v1(12.86,55.29) v1(13.37,47.04) v1(13.37,19.99) v1(13.37,19.35) v1(13.62,41.32) v1(13.62,39.93) v1(13.62,38.28) v1(13.62,36.75) v1(13.75,43.86) v1(13.77,33.23) v1(13.77,32.6) v1(13.88,13.13) v1(14.13,29.39) v1(14.26,59.23) v1(14.62,59.84) v1(14.64,55.04) v1(14.64,53.77) v1(14.76,51.87) v1(14.76,17.32) v1(14.76,15.8) v1(14.76,14.27) v1(14.82,6.11) v1(14.89,59.23) v1(15.09,56.72) v1(15.27,54.41) v1(15.4,51.87) v1(15.4,24.31) v1(15.65,49.83) v1(15.65,49.07) v1(15.91,55.04) v1(15.91,53.77) v1(16.03,30.78) v1(16.03,28.75) v1(16.16,46.91) v1(16.29,17.32) v1(16.29,15.8) v1(16.29,14.27) v1(16.67,42.47) v1(16.67,24.94) v1(16.67,24.31) v1(16.8,50.72) v1(16.92,45.01) v1(16.92,43.86) v1(17.04,29.76) v1(17.05,36.5) v1(17.05,10.97) v1(17.3,56.82) v1(17.43,50.72) v1(17.43,48.56) v1(17.67,59.84) v1(17.81,17.32) v1(17.81,15.8) v1(17.81,14.27) v1(17.87,6.11) v1(18.02,42.63) v1(18.07,30.78) v1(18.07,28.75) v1(18.63,40.51) v1(18.83,33.96) v1(19.18,52.63) v1(19.46,34.85) v1(19.57,38.15) v1(19.8,59.14) v1(19.97,57.2) v1(20.61,54.91) v1(20.61,54.28) v1(20.61,19.86) v1(20.61,19.23) v1(20.72,59.84) v1(20.92,6.11) v1(21.37,27.74) v1(21.75,38.66) v1(22,42.21) v1(22,26.59) v1(22.64,26.59) v1(22.77,42.21) v1(22.89,37.01) v1(22.89,36.37) v1(23.3,38.4) v1(23.53,42.21) v1(23.65,14.65) v1(23.77,59.84) v1(24.29,11.48) v1(24.42,40.31) v1(24.8,20.62) v1(24.92,37.46) v1(24.92,11.48) v1(25.05,40.31) v1(25.43,20.62) v1(25.81,40.31) v1(26.11,1.3) v1(26.45,20.62) v1(26.7,39.29) v1(26.7,38.15) v1(26.81,59.84) v1(26.96,1.45) v1(27.08,20.62) v1(27.29,38.74) v1(27.59,1.45) v1(27.85,39.29) v1(27.85,38.15) v1(28.1,20.62) v1(28.35,59.84) v1(28.61,1.45) v1(28.73,20.62) v1(28.86,10.46) v1(29.12,2.97) v1(29.12,2.34) v1(29.11,0.76) v1(29.24,1.45) v1(30.51,38.91) v1(30.64,12.5) v1(30.77,45.9) v1(30.89,44.5) v1(31.66,27.74) v1(31.65,0.76) v1(32.8,48.44) v1(32.93,29.74) v1(33.56,29.77) v1(33.94,48.44) v1(33.94,34.21) v1(34.45,39.11) v1(34.58,48.44) v1(35.21,52.12) v1(35.54,32.74) v1(36.61,26.85) v1(37.24,26.85) v1(37.42,51.08) v1(37.74,59.84) v1(38.24,32.34) v1(38.24,29.29) v1(38.45,22.75) v1(38.51,25.96) v1(38.51,25.32) v1(38.64,43.61) v1(38.82,45.01) v1(39.01,59.84) v1(39.01,51.04) v1(39.01,50.4) v1(39.21,0.76) v1(39.56,26.54) v1(39.78,53.64) v1(40.16,43.86) v1(40.42,46.28) v1(41.24,42.06) v1(41.31,54.55) v1(41.49,22.75) v1(41.56,25.45) v1(42.05,59.84) v1(42.2,48.56) v1(42.2,43.61) v1(42.26,6.86) v1(42.26,0.76) v1(43.61,21.34) v1(44.34,44.81) v1(44.36,47.86) v1(45.1,59.84) v1(45.32,23.86) v1(45.3,0.76) v1(45.63,47.86) v1(45.61,44.81) v1(45.61,19.03) v1(45.61,15.99) v1(45.61,12.94) v1(45.61,9.89) v1(45.61,6.84) v1(45.61,3.79) v1(46.74,55.87) v1(46.74,52.82) v1(48.01,55.87) v1(48.01,52.82)
ADDR: length 1.9
  TOP w0.109: R27313.2 v1(9.3,39.21) R27314.1
  BOTTOM w0.114: U2.19 v1(9.3,39.21)
BTN_ANALOG: length 3.2
  BOTTOM w0.114: TP110.1 6.51,25.2 6.13,25.58 5.49,25.58 5.27,25.35 J13.17
CE_USB: length 2.2
  BOTTOM w0.114: U2.36 14.56,42.26 15.53,43.23 R27327.1
CEQ: length 3.4
  BOTTOM w0.114: U2.48 15.1,37.81 15.48,37.44 R27318.1 15.94,37.71 16.05,37.83 16.87,37.83 17.08,37.62 R27317.2
CHARGER_SUB_BATGONE: length 2.6
  BOTTOM w0.114: R1008.2 12.85,13.1 12.61,13.35 12.61,13.77 13.24,14.4 U9.22
CHARGER_SUB_CMPOUT_OD: length 1.3
  BOTTOM w0.114: U9.30 13.6,17.6 13.12,18.08 R1010.1
DPEQ: length 1.9
  TOP w0.109: R27315.2 v1(9.3,40.26) R27316.1
  BOTTOM w0.114: U2.22 v1(9.3,40.26)
EC_I2C_USB_C1_SCL: length 71.8
  TOP w0.109: v1(32.8,44.25) 33.21,44.66 U7.3 ; v1(13.75,18.2) 14.07,18.2 15.35,19.48 15.65,19.48 v1(16.16,19.99)
  IN1 w0.097: v1(6.38,23.8) 6.89,23.29 7.37,23.29 12.02,18.65 13.3,18.65 v1(13.75,18.2) ; v1(32.8,44.25) 32.16,44.88 32.16,45.52 31.15,46.53 29.75,46.53 27.03,43.81 20.05,43.81 17.77,46.09 11.91,46.09 10.17,44.35 10.17,43.64 v1(10.57,43.23)
  IN4 w0.089: v1(6.38,23.8) 6.11,23.8 4.41,25.5 4.41,39.24 8.34,43.17 10.51,43.17 v1(10.57,43.23)
  BOTTOM w0.114: J13.14 6.33,23.85 v1(6.38,23.8) ; v1(16.16,19.99) 16.16,19.73 16.09,19.66 U9.35 ; U2.28 11.13,42.68 v1(10.57,43.23) ; v1(13.75,18.2) U9.31
EC_I2C_USB_C1_SDA: length 74.8
  TOP w0.109: U7.4 33.61,44.43 v1(32.8,43.61) ; v1(15.53,19.99) 14.38,18.85 v1(13.75,18.85)
  IN1 w0.097: v1(32.8,43.61) 32.29,44.12 32.29,44.37 31.97,44.7 31.97,45.43 31.07,46.33 29.83,46.33 27.11,43.61 19.97,43.61 17.69,45.9 12.1,45.9 10.57,44.37 v1(10.57,43.99) ; v1(7.14,23.8) 12.1,18.85 v1(13.75,18.85)
  IN4 w0.089: v1(7.14,23.8) 6.64,24.31 5.87,24.31 4.6,25.58 4.6,39.17 8.41,42.98 9.68,42.98 9.94,42.72 10.95,42.72 11.08,42.85 11.08,43.48 v1(10.57,43.99)
  BOTTOM w0.114: U9.32 14.89,18.72 14.76,18.85 v1(13.75,18.85) ; U9.34 15.69,19.83 v1(15.53,19.99) ; v1(10.57,43.99) 11.34,43.23 11.34,42.91 11.48,42.77 U2.29 ; J13.15 6.59,24.35 v1(7.14,23.8)
EN_KB_BL: length 3
  BOTTOM w0.114: J12.11 5.24,50.85 TP108.1
EN_PP3300_SUB_S: length 1.1
  TOP w0.109: R23.2 9.43,57.45 9.5,57.38 U3.4
EN_PP5000_PEN: length 2.5
  BOTTOM w0.114: J12.8 5.9,49.35 6.38,49.83 TP105.1
EN_PP5000_SUB_U: length 1.2
  TOP w0.109: R24.2 34.67,31.26 34.63,31.22 U4.4
EN_SUB_RAILS: length 105.2
  TOP w0.109: R24.1 35.08,27.86 v1(34.83,27.61) ; v1(8.8,58.44) R23.1
  IN1 w0.097: v1(8.8,58.44) 6.23,58.44 1.81,54.02 1.81,20.88 4.99,17.7 v1(9.68,17.7) 10.32,18.34 10.8,18.34 12.73,16.41 12.73,15.29 12.48,15.04 11.84,15.04 10.7,13.89 10.7,13.51 11.06,13.16 12.07,13.16 12.86,12.37 21.37,12.37 21.62,12.62 25.43,12.62 26.58,11.48 28.48,11.48 35.97,18.97 35.97,27.23 35.59,27.61 v1(34.83,27.61)
  BOTTOM w0.114: R1010.2 12.1,18.08 12,18.18 R22.1 10.16,18.18 v1(9.68,17.7)
EN_USB_A1_VBUS: length 41.8
  TOP w0.109: v1(32.42,36.37) 32.26,36.53 R375.1 31.78,36.24 31.25,35.71 27.24,35.71 26.54,36.4 U37.5
  BOTTOM w0.114: v1(32.42,36.37) 32.14,36.37 28.73,39.77 28.73,41.45 26.83,43.36 21.83,43.36 16.62,48.56 12.1,48.56 11.72,48.94 8.45,48.94 7.35,47.85 J12.5
KB_BL_PWM: length 2.7
  BOTTOM w0.114: J12.10 6.14,50.35 TP107.1
LID_360_L: length 14.9
  BOTTOM w0.114: J12.19 6.45,54.85 7.4,55.8 11.34,55.8 12.22,54.91 12.22,54.41 12.86,53.77 12.86,52.63 14.52,50.97 CN1.5
LID_OPEN: length 13.9
  BOTTOM w0.114: J12.18 5.24,54.35 5.5,54.61 6.71,54.61 7.65,55.55 11.21,55.55 11.97,54.79 11.97,54.28 12.52,53.73 CN1.1
PEN_DET_ODL: length 3.6
  BOTTOM w0.114: R37.1 7.66,49.61 7.4,49.35 6.28,49.35 5.78,48.85 J12.7
PP1200_SUB_S_R: length 21.1
  TOP w0.203: R268.1 C22.1 v1(12.48,58.44)
  IN1 w0.508: v1(12.48,58.44) 10.04,58.44 5.49,53.9 5.49,45.52 6.13,44.88 v1(7.65,44.88)
PP3300_SUB_LDO_G: length 76.4
  TOP w0.508: v1(12.48,59.1) 12.95,59.1 R20.1
  IN1 w0.508: v1(12.23,15.54) 12.23,16.3 10.83,17.7 v1(10.45,17.7) 10.45,17.58 9.94,17.07 4.86,17.07 1.4,20.53 1.4,54.37 6.13,59.1 v1(12.48,59.1) 12.83,59.1 13.34,58.6 13.34,57.8 11.97,56.44 11.97,54.28 13.88,52.37 13.88,51.1 v1(13.49,50.72)
  BOTTOM w0.203: U9.25 13.29,15.6 13.11,15.42 ; v1(10.45,17.7) 11.27,17.7 11.3,17.73 R22.2
  BOTTOM w0.381: v1(12.23,15.54) C187.1 12.48,14.78 13.11,15.42
PP3300_SUB_S: length 48.3
  IN1 w0.508: v1(18.96,27.79) 10.62,27.79 7.27,24.43 5.37,24.43 4.86,24.94 4.86,43.1 v1(6,44.25)
  IN4 w0.508: v1(6,44.25) 5.37,44.88 5.37,47.42 v1(6.26,48.31)
  BOTTOM w0.203: v1(6.26,48.31) 7.4,48.31 8.7,49.61 R27329.1
  BOTTOM w0.508: R21.1 8.89,47.26 6.64,45.01 6.51,45.01 6,44.5 v1(6,44.25)
  vias: v1(15.96,33.37) v1(15.96,32.74) v1(19.59,27.79)
PP3300_USB_C1_G: length 57.7
  TOP w0.178: C167.1 14.51,56.78 14.47,56.75 U8.10
  TOP w0.203: C167.1 13.75,57.1 R20.2
  TOP w0.508: v1(13.88,55.93) 13.88,56.18 13.37,56.69 R20.2
  IN1 w0.508: v1(31.4,47.42) 31.4,48.06 30.77,48.69 30.77,51.87 26.19,56.44 18.07,56.44 17.56,55.93 v1(13.88,55.93)
  IN4 w0.508: v1(13.88,55.93) 13.62,55.68 13.62,51.87 14.51,50.98 14.51,47.42 15.78,46.15 15.78,42.21 16.16,41.83 16.16,35.74 v1(16.81,35.1)
  BOTTOM w0.457: R27311.1 v1(16.81,35.1)
  BOTTOM w0.508: v1(37.5,45.9) 32.93,45.9 v1(31.4,47.42)
PP3300_USB_C1_U: length 36.4
  TOP w0.203: R27313.1 R27315.1 v1(7.06,40.26)
  TOP w0.508: v1(18.7,38.15) 18.7,38.28 19.41,38.98 19.41,39.49 19.02,39.88 18.22,39.88 v1(17.91,40.18)
  IN1 w0.508: v1(7.06,40.26) 7.06,43.95 v1(6.76,44.25)
  BOTTOM w0.203: R27327.2 17.56,43.23 ; R210.1 13.21,46.28 ; v1(17.91,40.18) R84.1
  BOTTOM w0.508: v1(6.76,44.25) 8.2,44.25 R27312.1 8.58,45.55 9.08,46.06 R21.2 10.86,46.06 11.08,46.28 16.67,46.28 18.64,44.31 ; 18.64,44.31 20.61,42.34 20.61,40.18 18.7,38.28 v1(18.7,38.15) ; 18.64,44.31 17.56,43.23
PP5000_SUB_CHARGER_INT: length 28.6
  IN4 w0.508: v1(11.34,13.65) 12.22,12.76 12.22,12.24 15.15,9.32 17.56,9.32 21.37,13.13 24.01,13.13 24.92,14.05 24.92,17.41 v1(22.38,19.95)
  BOTTOM w0.203: U9.23 13.13,14.8 12.35,14.02 12.35,13.9 C200.1
  BOTTOM w0.381: v1(11.34,13.65) C200.1 ; R1004.2 v1(22.38,19.95)
PP5000_SUB_CHARGER_INT_R: length 3.3
  BOTTOM w0.203: C202.1 19.45,17.69 19.36,17.6 U9.1
  BOTTOM w0.381: R1004.1 20.44,17.69 C202.1
PP5000_SUB_U: length 25.6
  TOP w0.203: R27304.1 R27303.1 R27302.1 31.02,37.26 30.77,37.51 v1(30.36,37.51) ; R27307.1 25.21,36.15 24.15,35.09 C1019.1
  IN1 w0.508: v1(13.75,26.34) 19.34,26.34 20.48,27.48 20.48,35.23
  BOTTOM w0.381: v1(13.75,26.34) 13.75,23.66 R1011.2
  vias: v1(20.35,36.63) v1(20.99,36.63) v1(23.3,39.29) v1(23.93,39.29)
PP5000_SUB_U_R: length 17.5
  TOP w0.203: C258.1 R271.1 v1(34.83,26.97)
  TOP w0.508: v1(22,28.37) 20.73,29.64 20.73,30.15
  IN1 w0.508: v1(22,28.37) 22.64,27.74 30.64,27.74 31.27,28.37 32.93,28.37 34.32,26.97 v1(34.83,26.97)
PP5000_USB_A1_VBUS:
  vias: v1(29.37,40.94) v1(29.37,40.31)
PP5000_USB_C1_VCONN: length 2.9
  BOTTOM w0.203: U9.33 15.29,19.22 C1012.1 14.9,20.11 14.76,20.24 R1011.1
PPVAR_SYS: length 21.7
  TOP w0.203: R1013.1 10.93,24.01 11.89,24.01 12.1,23.81 U1000.1
  IN4 w0.508: 12.22,22.66 14,20.88 14,19.61 15.53,18.08 17.94,18.08 21.37,14.65 v1(23.02,14.65)
  BOTTOM w0.203: 19.46,15.29 19.37,15.2 U9.7
  BOTTOM w0.381: 19.46,15.29 20,15.29 20.64,14.65 v1(23.02,14.65)
  vias: v1(6.26,22.78) v1(6.26,22.15) v1(6.26,21.13) v1(6.26,20.5) v1(6.51,57.2) v1(6.51,56.56) v1(6.51,55.93) v1(6.89,22.78) v1(6.89,22.15) v1(7.02,21.26) v1(7.65,21.26) v1(25.31,34.21) v1(25.94,34.21)
PPVAR_SYS_N: length 36.7
  TOP w0.381: R1013.2 v1(9.05,23.67)
  IN1 w0.381: v1(28.35,12.88) 28.35,12.5 28.08,12.23 27.35,12.23 23.86,15.72 20.43,15.72 17.43,18.72 15.15,18.72 14.2,19.66 14.2,20.14 10.47,23.87 9.25,23.87 v1(9.05,23.67)
  BOTTOM w0.203: 19.59,14.78 19.57,14.8 U9.8
  BOTTOM w0.381: 19.59,14.78 20.3,14.07 24.5,14.07 C1017.2 25.52,14.36 25.66,14.5 C1018.1 26.8,14.02 27.46,14.02 28.35,13.13 v1(28.35,12.88)
PPVAR_SYS_P: length 34.6
  TOP w0.381: R1012.1 v1(9.05,24.69)
  IN1 w0.381: v1(27.62,12.88) 24.22,16.28 20.66,16.28 17.66,19.28 15.38,19.28 14.76,19.89 14.76,20.37 10.7,24.43 9.3,24.43 v1(9.05,24.69)
  BOTTOM w0.203: 19.33,14.27 19.21,14.4 U9.9
  BOTTOM w0.381: v1(27.62,12.88) 27.62,13.13 27.24,13.51 26.8,13.51 C1016.1 25.66,13.03 25.52,13.17 C1017.1 24.45,13.51 20.09,13.51 19.33,14.27
PPVAR_SYS_R: length 35.3
  TOP w0.203: R1012.2 10.93,24.34 11.89,24.34 12.1,24.55 U1000.2
  IN4 w0.508: v1(13.11,26.21) 13.11,22.78 14.64,21.26 14.64,19.86 15.78,18.72 18.19,18.72 21.41,15.5 23.78,15.5 24.29,14.99 24.29,14.27 23.78,13.77 20.86,13.77 19.59,12.5 13.62,12.5 13.11,13 v1(13.11,13.64)
  BOTTOM w0.203: U9.21 13.47,14 v1(13.11,13.64)
PPVAR_USB_C1_VBUS: length 1.2
  TOP w0.254: J11.A4 41.74,52.55
  vias: v1(9.56,9.83) v1(10.19,9.83) v1(26.7,6.02) v1(26.7,5.38) v1(27.34,6.02) v1(27.34,5.38) v1(28.35,6.02) v1(28.35,5.38) v1(28.99,6.02) v1(28.99,5.38) v1(37.24,52.75) v1(37.24,52.12) v1(37.88,53.39) v1(37.88,52.75) v1(38.51,53.39) v1(38.51,52.75)
PPVAR_USB_C1_VIN: length 2.3
  TOP w0.203: U18.1 26.19,12.25 25.99,12.46 25.02,12.46 R224.1
PPVAR_USB_C1_VIN_R: length 2.3
  TOP w0.203: R226.2 25.02,12.79 25.99,12.79 26.19,12.99 U18.2
SSEQ: length 3.7
  BOTTOM w0.114: R27319.2 17.46,38.24 17.29,38.07 16.09,38.07 15.94,38.22 R27320.1 15.78,38.5 15.65,38.63 15.27,38.63 15.15,38.51 U2.46
SUB_CHARGER_COMPF: length 5.2
  BOTTOM w0.114: R1003.1 C1008.1 19.84,11.49 19.34,11.99 18.28,11.99 17.69,12.58 U9.12
SUB_CHARGER_COMPR: length 4
  BOTTOM w0.114: U9.13 17.29,12.64 18.06,11.87 C1010.1 R1005.1
USB_A0_STATUS_L: length 27.8
  TOP w0.109: v1(23.78,36.75) 24.13,36.4 R27333.1
  BOTTOM w0.114: v1(23.78,36.75) 23.78,37.01 22.84,37.95 22.84,39.47 21.5,40.82 21.5,42.67 16.36,47.8 11.76,47.8 11.36,48.19 8.72,48.19 6.75,46.23 5.95,46.23 5.57,45.85 J12.1
USB_A1_CHARGE_EN_L: length 26.1
  TOP w0.109: v1(22.38,38.66) 22.2,38.47 Q38.2 ; v1(6.26,45.77) v1(6.26,47.04)
  BOTTOM w0.114: v1(6.26,45.77) 6.64,45.77 8.77,47.9 11.31,47.9 11.66,47.56 16.26,47.56 21.25,42.57 21.25,40.72 22.38,39.59 v1(22.38,38.66) ; v1(6.26,47.04) 5.75,47.04 5.56,46.85 J12.3
USB_A1_ILIM_SEL: length 5
  TOP w0.109: U37.4 25.69,37.64 26.07,37.27 26.07,36.63 25.94,36.5 R27307.2 25.66,36.91 25.56,37.01 25.05,37.01 24.9,36.85 R27333.2 24.54,37.13 24.16,37.51 Q38.3
USB_A1_OC_ODL: length 28.2
  TOP w0.109: v1(28.23,41.32) 28.04,41.14 U37.13
  BOTTOM w0.114: v1(28.23,41.32) 26.58,42.98 21.87,42.98 16.53,48.31 11.97,48.31 11.58,48.7 8.55,48.7 7.39,47.55 5.75,47.55 5.55,47.35 J12.4
USB_A1_SSRX_C_N: length 1.6
  BOTTOM w0.097: U1.23 14.46,30.51 14.31,30.35 13.88,30.35 C157.2
USB_A1_SSRX_C_P: length 1.6
  BOTTOM w0.097: U1.22 14.46,30.01 14.31,30.17 13.88,30.17 C156.2
USB_A1_SSRX_N: length 8.9
  BOTTOM w0.097: C157.1 12.85,30.35 11.65,30.35 11.31,30.69 5.3,30.69 5.14,30.85 J13.28
USB_A1_SSRX_P: length 8.9
  BOTTOM w0.097: J13.27 5.14,30.35 5.3,30.51 11.23,30.51 11.57,30.17 12.85,30.17 C156.1
USB_A1_SSRX_U_N: length 23.1
  BOTTOM w0.097: J10.5 35.84,37.64 35.21,37.64 33.48,35.92 22.31,35.92 20.48,34.09 20.48,30.73 20.1,30.35 19.77,30.35 19.62,30.51 U1.8
USB_A1_SSRX_U_P: length 23.1
  BOTTOM w0.097: U1.9 19.62,30.01 19.77,30.17 20.18,30.17 20.67,30.66 20.67,34.02 22.38,35.74 33.56,35.74 35.28,37.46 35.84,37.46 J10.6
USB_A1_SSTX_C_N: length 1.6
  BOTTOM w0.097: C1.2 13.88,28.85 14.31,28.85 14.46,29.01 U1.20
USB_A1_SSTX_C_P: length 1.6
  BOTTOM w0.097: U1.19 14.46,28.51 14.31,28.67 13.88,28.67 C2.2
USB_A1_SSTX_CON_N: length 23.7
  BOTTOM w0.097: C6.2 20.99,28.85 21.13,28.85 21.24,28.97 21.24,33.96 22.62,35.34 30.53,35.34 34.22,31.64 35.84,31.64 J10.8
USB_A1_SSTX_CON_P: length 23.7
  BOTTOM w0.097: J10.9 35.84,31.46 34.15,31.46 30.45,35.15 22.7,35.15 21.43,33.88 21.43,28.89 21.21,28.67 20.99,28.67 C5.2
USB_A1_SSTX_N: length 8.9
  BOTTOM w0.097: J13.25 5.14,29.35 5.3,29.19 11.03,29.19 11.37,28.85 12.85,28.85 C1.1
USB_A1_SSTX_P: length 8.9
  BOTTOM w0.097: J13.24 5.14,28.85 5.3,29.01 10.95,29.01 11.29,28.67 12.85,28.67 C2.1
USB_A1_SSTX_U_N: length 1.4
  BOTTOM w0.097: C6.1 19.97,28.85 19.77,28.85 19.62,29.01 U1.11
USB_A1_SSTX_U_P: length 1.4
  BOTTOM w0.097: U1.12 19.62,28.51 19.77,28.67 19.97,28.67 C5.1
USB_A1_STATUS_L: length 31.3
  TOP w0.109: U37.9 v1(29.85,37.99)
  BOTTOM w0.114: J12.2 5.69,46.35 5.87,46.53 6.72,46.53 8.62,48.44 11.46,48.44 11.84,48.06 16.45,48.06 21.78,42.72 25.12,42.72 v1(29.85,37.99)
USB_A1_USB2_L_N: length 7.7
  TOP w0.097: J10.2 36.51,33.55 35.72,34.34 35.21,34.34 35.08,34.21 34.64,34.21 34.36,34.5 34.36,34.71 33.97,35.1 33.97,35.98 34.26,36.26 D2744.1 34.26,36.82 34.36,36.91 34.36,37.24 L6.3
USB_A1_USB2_L_P: length 7.7
  TOP w0.097: L6.2 34.54,37.24 34.54,36.91 34.64,36.82 D2744.2 34.64,36.26 34.93,35.98 34.93,35.1 34.54,34.71 34.54,34.58 34.72,34.4 35.01,34.4 35.13,34.52 35.75,34.52 35.85,34.62 35.85,34.97 36.42,35.55 J10.3
USB_A1_USB2_N: length 28
  TOP w0.097: U37.2 25.02,38.99 24.87,38.83 24.47,38.83 24.25,38.62 24.25,38.49 v1(23.95,38.19)
  IN1 w0.097: v1(6.66,27.97) 6.93,27.7 8.6,27.7 12.65,31.75 13.66,31.75 14.64,32.72 14.64,33.2 15.65,34.21 17.1,34.21 18.12,35.23 18.12,36.8 19,37.68 24.13,37.68 24.22,37.78 24.22,37.92 v1(23.95,38.19)
  BOTTOM w0.097: J13.22 5.14,27.85 5.3,27.69 6.38,27.69 v1(6.66,27.97)
USB_A1_USB2_P: length 28
  TOP w0.097: U37.3 25.02,38.49 24.87,38.65 24.54,38.65 24.43,38.54 24.43,38.45 v1(24.7,38.19)
  IN1 w0.097: v1(6.66,27.23) 6.93,27.5 8.69,27.5 12.73,31.55 13.75,31.55 14.84,32.64 14.84,33.11 15.74,34.01 17.19,34.01 18.32,35.14 18.32,36.72 19.08,37.48 24.21,37.48 24.43,37.7 24.43,37.92 v1(24.7,38.19)
  BOTTOM w0.097: J13.21 5.14,27.35 5.3,27.51 6.38,27.51 v1(6.66,27.23)
USB_A1_USB2_U_N: length 7.8
  TOP w0.097: L6.4 34.26,37.85 34.36,37.95 34.36,38.31 v1(34.08,38.59) ; U37.11 29.56,38.99 29.72,38.83 29.95,38.83 30.33,38.46 30.87,38.46 v1(31.15,38.74)
  BOTTOM w0.097: v1(34.08,38.59) 34.26,38.59 34.36,38.5 34.36,38.19 34.25,38.08 33.25,38.08 32.89,38.44 31.24,38.44 31.15,38.53 v1(31.15,38.74)
USB_A1_USB2_U_P: length 7.9
  TOP w0.097: v1(34.82,38.59) 34.54,38.31 34.54,38.04 L6.1 ; v1(31.15,38) 30.87,38.28 30.25,38.28 29.88,38.65 29.72,38.65 29.56,38.49 U37.10
  BOTTOM w0.097: v1(31.15,38) 31.4,38.25 32.82,38.25 33.17,37.9 34.32,37.9 34.54,38.11 34.54,38.31 v1(34.82,38.59)
